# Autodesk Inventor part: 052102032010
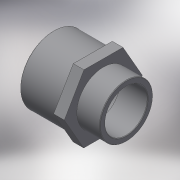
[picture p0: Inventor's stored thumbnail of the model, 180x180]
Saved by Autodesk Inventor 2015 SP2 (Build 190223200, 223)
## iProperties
Created: 2017-10
Part Number: 052102032010
Material: Generic
Description: PLASSON SOCKET NIPPLE THR-CE 40(32)-1"
Document SubType Name: Modeling
Designer: KIM
Density: 1 g/cm^3
Appearance: Default
Author: KIM
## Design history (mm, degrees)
derived "052102.ipt"
feature "Solid1::052102.ipt"
tag "TaggingFeature1"
body "Solid1"
other parameters: "d0" = 62, "d2" = 46.5, "d13" = 0, "d14" = 0.32, "d17" = 26, "d18" = 22.8, "d20" = 32, "d21" = 33.249, "d22" = 22, "d23" = 30.4, "d24" = 26.5992, "d25" = 19, "d26" = -26, "d_" = 32, "R_" = 33.249, "C_" = 46.5, "B_" = 12, "L_" = 26, "lt_" = 19, "H_" = 62, "l_" = 22
